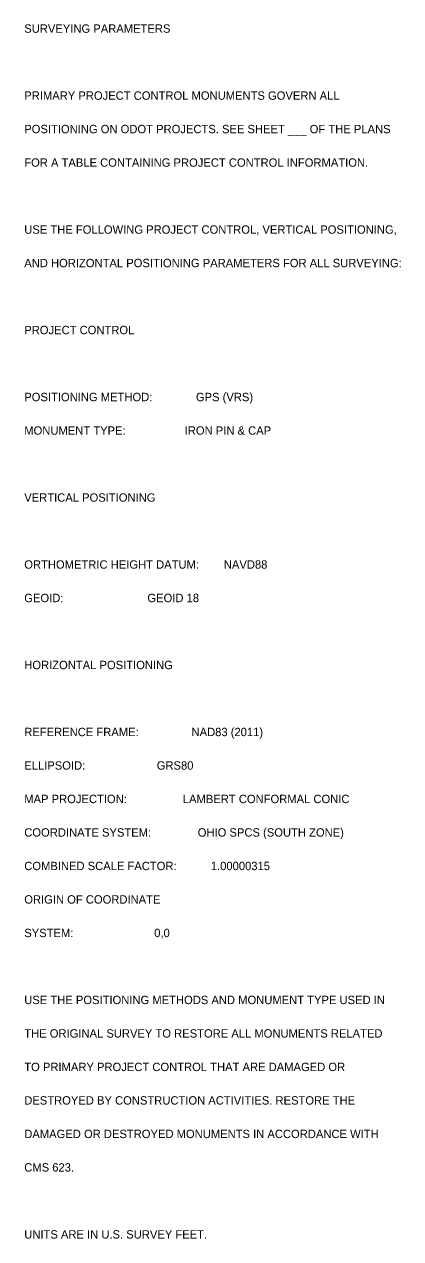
# Model space of a CAD drawing. Extents: x -2 to 1979875, y -2 to 232027.
# Drawn here: x 1979811.6 to 1979874.5, y 231268.8 to 231471.9 of the extents above; entities that cross this region are included whole.
import ezdxf

# ---------------------------------------------------------------- set-up
doc = ezdxf.new("R2010")
doc.units = 0
doc.layers.add('SH_Text', color=7, linetype='Continuous')

msp = doc.modelspace()

# ---------------------------------------------------------------- texts
at = {"layer": 'SH_Text'}
for s, p in [('SURVEYING PARAMETERS', (1979811.57, 231470.45)), ('PRIMARY PROJECT CONTROL MONUMENTS GOVERN ALL', (1979811.57, 231459.25)), ('POSITIONING ON ODOT PROJECTS. SEE SHEET ___ OF THE PLANS', (1979811.57, 231453.65)), ('FOR A TABLE CONTAINING PROJECT CONTROL INFORMATION.', (1979811.57, 231448.05)), ('USE THE FOLLOWING PROJECT CONTROL, VERTICAL POSITIONING,', (1979811.57, 231436.85)), ('AND HORIZONTAL POSITIONING PARAMETERS FOR ALL SURVEYING:', (1979811.57, 231431.25)), ('PROJECT CONTROL', (1979811.57, 231420.05)), ('POSITIONING METHOD:              GPS (VRS)', (1979811.57, 231408.85)), ('MONUMENT TYPE:                   IRON PIN & CAP', (1979811.57, 231403.25)), ('VERTICAL POSITIONING', (1979811.57, 231392.05)), ('ORTHOMETRIC HEIGHT DATUM:        NAVD88', (1979811.57, 231380.85)), ('GEOID:                           GEOID 18', (1979811.57, 231375.25)), ('HORIZONTAL POSITIONING', (1979811.57, 231364.05)), ('REFERENCE FRAME:                 NAD83 (2011)', (1979811.57, 231352.85)), ('ELLIPSOID:                       GRS80', (1979811.57, 231347.25)), ('MAP PROJECTION:                  LAMBERT CONFORMAL CONIC', (1979811.57, 231341.65)), ('COORDINATE SYSTEM:               OHIO SPCS (SOUTH ZONE)', (1979811.57, 231336.05)), ('COMBINED SCALE FACTOR:           1.00000315', (1979811.57, 231330.45)), ('ORIGIN OF COORDINATE', (1979811.57, 231324.85)), ('SYSTEM:                          0,0', (1979811.57, 231319.25)), ('USE THE POSITIONING METHODS AND MONUMENT TYPE USED IN', (1979811.57, 231308.05)), ('THE ORIGINAL SURVEY TO RESTORE ALL MONUMENTS RELATED', (1979811.57, 231302.45)), ('TO PRIMARY PROJECT CONTROL THAT ARE DAMAGED OR', (1979811.57, 231296.85)), ('DESTROYED BY CONSTRUCTION ACTIVITIES. RESTORE THE', (1979811.57, 231291.25)), ('DAMAGED OR DESTROYED MONUMENTS IN ACCORDANCE WITH', (1979811.57, 231285.65)), ('CMS 623.', (1979811.57, 231280.05)), ('UNITS ARE IN U.S. SURVEY FEET.', (1979811.57, 231268.85))]:
    msp.add_text(s, height=1.4, dxfattribs=at).set_placement(p)

doc.saveas('drawing.dxf')
